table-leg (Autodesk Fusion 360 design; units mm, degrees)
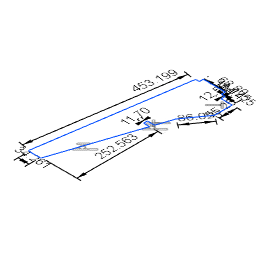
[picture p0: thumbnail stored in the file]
sketch "legs4" plane through (0, 0, 0) normal (0, 1, 0) x axis (1, 0, 0)
  dimension "d4" = 11.7
  dimension "d5" = 12.55
  dimension "d6" = 453.1987
  dimension "d7" = 86.0233
  dimension "d8" = 55.25
  dimension "d9" = 34.425
  dimension "d10" = 11.475
  dimension "d11" = 68.8
  dimension "d12" = 34.2613
  dimension "d13" = 252.5628
sketch "top-table-slots" plane through (0, 0, 0) normal (0, 1, 0) x axis (1, 0, 0)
